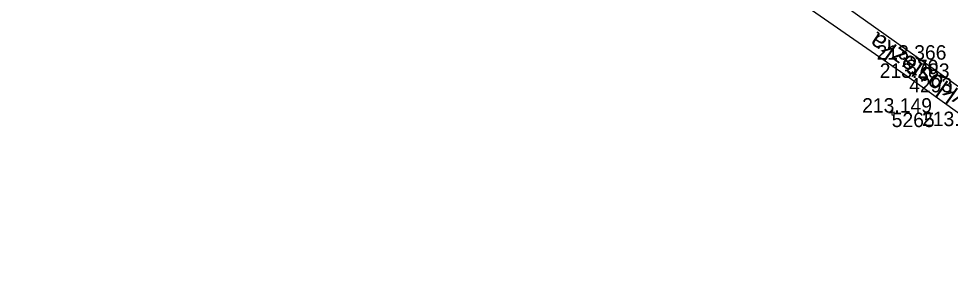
# Model space of a CAD drawing. Extents: x -556590 to -554855, y -1137918 to -1135717.
# Drawn here: x -556102.5 to -556025.1, y -1136102.8 to -1136082.2 of the extents above; entities that cross this region are included whole.
import ezdxf

# ---------------------------------------------------------------- set-up
doc = ezdxf.new("R2010")
doc.units = 0
for name, color, linetype in [('Vrstva 49', 7, 'Continuous'), ('Vrstva 51', 7, 'Continuous'), ('Vrstva 60', 7, 'Continuous'), ('Vrstva 61', 7, 'Continuous')]:
    doc.layers.add(name, color=color, linetype=linetype)

msp = doc.modelspace()

# ---------------------------------------------------------------- linework, layer by layer
at = {"layer": 'Vrstva 49'}
for p, q in [((-556028.978, -1136085.781), (-556028.624, -1136085.427)), ((-556028.624, -1136085.781), (-556028.978, -1136085.427)), ((-556029.754, -1136089.953), (-556030.246, -1136090.047)), ((-556030.047, -1136089.754), (-556029.953, -1136090.246))]:
    msp.add_line(p, q, dxfattribs=at)
at = {"layer": 'Vrstva 51'}
for points in [[(-556003.109, -1136102.758), (-556006.375, -1136101.225), (-556010.882, -1136098.948), (-556015.231, -1136096.337), (-556020.327, -1136093.013), (-556028.542, -1136087.117), (-556040.188, -1136079.041), (-556043.827, -1136076.734), (-556048.783, -1136074.01), (-556065.089, -1136065.628), (-556077.857, -1136058.711), (-556079.979, -1136057.374), (-556081.878, -1136055.64), (-556083.273, -1136053.979), (-556084.513, -1136051.523), (-556088.912, -1136041.262), (-556090.343, -1136038.92), (-556092.002, -1136037.117), (-556093.982, -1136035.652), (-556110.016, -1136025.492), (-556130.533, -1136012.591), (-556156.21, -1135997.017)], [(-556020.931, -1136090.347), (-556037.809, -1136078.372), (-556042.535, -1136075.223), (-556047.808, -1136072.231), (-556065.635, -1136063.04), (-556077.899, -1136056.26), (-556079.86, -1136054.619), (-556081.334, -1136052.905), (-556082.602, -1136050.669), (-556085.661, -1136043.137), (-556087.32, -1136039.611), (-556088.581, -1136037.601), (-556090.361, -1136035.586), (-556092.441, -1136034.014), (-556114.655, -1136020.216), (-556135.009, -1136007.539)]]:
    msp.add_lwpolyline(points, dxfattribs=at)
at = {"layer": 'Vrstva 60'}
for p, q in [((-556028.801, -1136085.604), (-556028.801, -1136085.604)), ((-556028.542, -1136087.117), (-556028.542, -1136087.117)), ((-556030, -1136090), (-556030, -1136090))]:
    msp.add_line(p, q, dxfattribs=at)

# ---------------------------------------------------------------- texts
at = {"layer": 'Vrstva 51'}
msp.add_text('cyklostezka', height=1.5, rotation=144.64417, dxfattribs=at).set_placement((-556022.735, -1136089.247))
at = {"layer": 'Vrstva 60'}
for s, p in [('370', (-556028.801, -1136086.804)), ('4293', (-556028.542, -1136088.317)), ('5265', (-556030, -1136091.2))]:
    msp.add_text(s, height=1.2, dxfattribs=at).set_placement(p)
at = {"layer": 'Vrstva 61'}
for s, p in [('213.366', (-556031.253, -1136085.604)), ('213.283', (-556030.994, -1136087.117)), ('213.149', (-556032.454, -1136090)), ('213.131', (-556027.481, -1136091.119))]:
    msp.add_text(s, height=1.2, dxfattribs=at).set_placement(p)

doc.saveas('drawing.dxf')
